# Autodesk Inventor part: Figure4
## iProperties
Shininess: 77.0
Length Units: 11269
Angle Units: 11279
Time Units: 11290
Mass Units: 11283
Length Display Precision: 3
Angle Display Precision: 2
Created: 2001-12
Part Number: Figure4
Document SubType Name: Modeling
Designer: CADSoft
Density: 1 g/cm^3
Density: 0.0
Volumn: 0.0
Area: 0.0
PropertySet Name: Model Information
Control State: 0
Master: False
Checked Out: False
Author: CADSoft
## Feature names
1. Loft1
